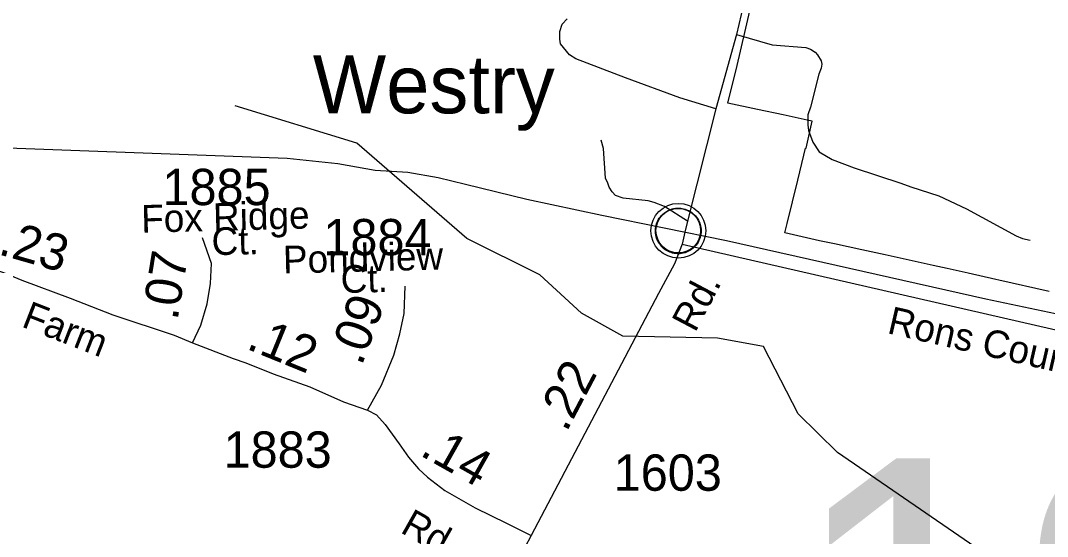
# Model space of a CAD drawing. Extents: x 2220236 to 2384410, y 720751 to 894131.
# Drawn here: x 2323811 to 2327342, y 806242 to 808018 of the extents above; entities that cross this region are included whole.
import ezdxf

# ---------------------------------------------------------------- set-up
doc = ezdxf.new("R2010")
doc.units = 0
doc.layers.add('Default', color=7, linetype='Continuous')

msp = doc.modelspace()

# ---------------------------------------------------------------- linework, layer by layer
at = {"layer": 'Default'}
for points in [[(2326568.2, 810272.9), (2326569.8, 810183), (2326568.1, 810143.3), (2326561.5, 810070.5), (2326543.3, 809895.2), (2326531.8, 809757.9), (2326513.6, 809552.8), (2326498.7, 809339.5), (2326493.8, 809233.6), (2326479.7, 809112.1), (2326464.8, 808978.1), (2326446.7, 808814.4), (2326408.6, 808584.5), (2326390.5, 808490.2), (2326369, 808399.3), (2326345.6, 808281.4), (2326273, 807970.7), (2326201.9, 807714.1), (2326104, 807327.2), (2326095.2, 807289.9)], [(2327347.8, 807086.1), (2327175, 807124.6), (2327164.2, 807127), (2327069.8, 807148.3), (2326997.2, 807164.6), (2326948.8, 807175.4), (2326804.8, 807207.2), (2326784.5, 807211.6), (2326703.5, 807229.1), (2326609.8, 807249.3), (2326558.5, 807260.3), (2326439.2, 807287), (2326447.2, 807319.7), (2326483.5, 807468.9), (2326504.2, 807554.4), (2326510.2, 807579.1), (2326512.8, 807579.1), (2326533.2, 807671.8), (2326516, 807675.5), (2326433.2, 807693.2), (2326345, 807712), (2326243.2, 807733.7), (2326274.8, 807863), (2326301.2, 807976.9), (2326331.5, 808107.6)], [(2327347.8, 807086.1), (2327175, 807124.6), (2327164.2, 807127), (2327069.8, 807148.3), (2326997.2, 807164.6), (2326948.8, 807175.4), (2326804.8, 807207.2), (2326784.5, 807211.6), (2326703.5, 807229.1), (2326609.8, 807249.3), (2326558.5, 807260.3), (2326439.2, 807287), (2326447.2, 807319.7), (2326483.5, 807468.9), (2326504.2, 807554.4), (2326510.2, 807579.1), (2326512.8, 807579.1), (2326533.2, 807671.8), (2326516, 807675.5), (2326433.2, 807693.2), (2326345, 807712), (2326243.2, 807733.7), (2326274.8, 807863), (2326301.2, 807976.9), (2326331.5, 808107.6)], [(2326201.9, 807714.1), (2326077.5, 807752.6), (2325890.8, 807820.6), (2325720.3, 807886.9), (2325698.1, 807900.6), (2325667.6, 807938.2), (2325665.5, 807954.3), (2325665.3, 807980.3), (2325673, 808006.2), (2325690.6, 808024.5)], [(2326273, 807970.7), (2326395.4, 807934.1), (2326511.4, 807925.4), (2326527.4, 807919.5), (2326543.6, 807909.7), (2326551.6, 807899.8), (2326563.8, 807879.9), (2326565.9, 807868), (2326564.1, 807853.9), (2326556.3, 807833.8), (2326527.6, 807719.6), (2326517.8, 807693.4), (2326518.2, 807659.6), (2326520.4, 807639.5), (2326534.9, 807599.7), (2326557.2, 807566), (2326601.5, 807540.4), (2326677.7, 807511.3), (2326838.3, 807459), (2326872.5, 807445.4), (2326968.8, 807414.5), (2327063.2, 807369.6), (2327234, 807277.3), (2327256.2, 807267.6), (2327282.3, 807261.9)], [(2318345.2, 807751.5), (2319665, 807707.7), (2320578.7, 807687.5), (2321488.8, 807653.4), (2322722.5, 807614.6), (2323518.4, 807589.3), (2324728.3, 807544.3), (2324902.4, 807526.2), (2325030.8, 807503.6), (2325142.6, 807496.8), (2325246.8, 807477.8), (2325341, 807454.9), (2325551.4, 807403.2), (2325809.9, 807348), (2326238.6, 807260.7), (2327130.5, 807060.4), (2328066, 806862.6), (2329318.5, 806586.2), (2329681.9, 806506.8), (2329765.5, 806488.4), (2329846, 806471)], [(2327373.9, 806063.9), (2327132, 806178.7), (2326619.9, 806532), (2326485, 806664.3), (2326365.9, 806895.8), (2326207, 806925.3), (2325881.9, 806931.8), (2325739.8, 807011.3), (2325596.9, 807143.3), (2325345.9, 807267.6), (2324967, 807596.7), (2324548.9, 807724.1)], [(2326104, 807327.2), (2326025.5, 807378.4), (2325989.4, 807391.9), (2325969.3, 807397.7), (2325883.3, 807406.8), (2325857.1, 807416.5), (2325845, 807428.4), (2325835, 807444.2), (2325830.8, 807458.3), (2325822.5, 807476.1), (2325815.5, 807578.1), (2325807.2, 807605.9)], [(2326095.2, 807289.9), (2326085.5, 807249), (2326059.1, 807181.2), (2326004.5, 807078.6), (2325566.3, 806246.1)], [(2324402.7, 806908.8), (2324431.3, 806970), (2324452.4, 807042.6), (2324463.8, 807113.4), (2324467.7, 807182.2), (2324437.1, 807270.2)], [(2326085.5, 807249), (2327880.4, 806836.6), (2328201.1, 806770), (2328830.1, 806646.9), (2328928.4, 806619.9), (2328946.3, 806612.2), (2328974.8, 806582.4), (2328987, 806562.7), (2328999.1, 806550.8), (2329023.4, 806518.9), (2329076, 806469.7), (2329104, 806459.8), (2329260.3, 806413.6), (2329290.6, 806402)], [(2323230.7, 807245.2), (2323276.2, 807219.9), (2323331.6, 807189.3), (2323369.8, 807181.7), (2323440.6, 807183.6), (2323515.1, 807191.2), (2323574.3, 807197), (2323608.7, 807195.1), (2323662.3, 807179.8), (2323752.1, 807151.1), (2323815.2, 807124.3), (2323981.4, 807063.1), (2324128.6, 807005.8), (2324338.8, 806935), (2324402.7, 806908.8)], [(2325004.3, 806677.7), (2325052, 806763.7), (2325094.1, 806867), (2325115.1, 806939.7), (2325130.3, 807009.9), (2325134.1, 807103.6)], [(2324402.7, 806908.8), (2324541.8, 806855.5), (2324585.7, 806840.2), (2324679.4, 806802), (2324805.5, 806758), (2324922.1, 806706.4), (2325004.3, 806677.7)], [(2325004.3, 806677.7), (2325034.5, 806660.7), (2325065.1, 806628.2), (2325112.9, 806561.3), (2325145.3, 806515.4), (2325179.7, 806475.3), (2325210.3, 806446.6), (2325269.6, 806400.7), (2325374.7, 806341.4), (2325481.7, 806287.9), (2325566.3, 806246.1)], [(2325566.3, 806246.1), (2325392.1, 805915.1), (2325262.5, 805626.4), (2324528.6, 804173.5), (2324435.7, 804015.1), (2324349.2, 803896.6), (2324302.1, 803839.5), (2324247.6, 803770), (2324118.9, 803647.6), (2324000.7, 803529.4), (2323914.1, 803455.5)]]:
    msp.add_lwpolyline(points, dxfattribs=at)
msp.add_lwpolyline([(2325995.2, 807307.1), (2325996.2, 807312.7), (2325998, 807319.3), (2326000.9, 807326.5), (2326003.9, 807332.2), (2326007.2, 807337.9), (2326011, 807343.1), (2326014.9, 807347.4), (2326019.5, 807352), (2326025, 807356.6), (2326030.5, 807360.3), (2326035.3, 807363.1), (2326040.4, 807365.6), (2326045.9, 807367.9), (2326051.5, 807369.7), (2326055.8, 807370.9), (2326060.7, 807371.6), (2326064.8, 807372.3), (2326071.2, 807372.6), (2326075.6, 807372.5), (2326081.3, 807372.2), (2326086.2, 807371.5), (2326091.1, 807370.5), (2326096.1, 807369.1), (2326101.2, 807367.2), (2326107.9, 807364.2), (2326114.2, 807360.7), (2326119.2, 807357.2), (2326124.4, 807353.2), (2326127.7, 807350), (2326131.8, 807345.7), (2326135.7, 807341), (2326138.8, 807336.4), (2326141.9, 807331.4), (2326144.3, 807326.2), (2326146.4, 807321.2), (2326147.9, 807316.2), (2326149.2, 807311.6), (2326150.3, 807305.5), (2326150.9, 807300.8), (2326151.2, 807294.8), (2326151, 807289.1), (2326150.5, 807283.4), (2326149.5, 807277.9), (2326147.9, 807271.7), (2326146, 807265.9), (2326143.7, 807260.8), (2326140.5, 807254.8), (2326137.2, 807249.5), (2326133.8, 807244.8), (2326129.6, 807240.1), (2326124.3, 807235.1), (2326119.3, 807231), (2326114.3, 807227.5), (2326109.9, 807225), (2326103.1, 807221.8), (2326096, 807219.1), (2326090, 807217.6), (2326083.4, 807216.3), (2326079, 807215.8), (2326074.5, 807215.6), (2326068.9, 807215.6), (2326064.6, 807216), (2326059, 807216.7), (2326053.1, 807218), (2326048.5, 807219.3), (2326043.3, 807221.2), (2326038.7, 807223.2), (2326034.8, 807225.4), (2326028, 807229.5), (2326022.4, 807233.8), (2326017.5, 807238.3), (2326013.1, 807243.1), (2326009.9, 807247.1), (2326006.9, 807251.3), (2326002.8, 807258.4), (2326001.1, 807261.9), (2325999.4, 807265.9), (2325996.8, 807274.1), (2325995.2, 807281.2), (2325994.6, 807286.3), (2325994.2, 807292.7), (2325994.2, 807297.3), (2325994.7, 807303.8)], close=True, dxfattribs=at)
for centre, radius in [((2326072.9, 807294.7), 94.3), ((2326072.6, 807295), 76.7)]:
    msp.add_circle(centre, radius, dxfattribs=at)

# ---------------------------------------------------------------- texts
for s, height, p in [('Westry', 200, (2324815.9, 807698.9)), ('1885', 125, (2324299.1, 807382.8)), ('1884', 125, (2324852.3, 807210.2)), ('1883', 125, (2324509.2, 806479)), ('1603', 125, (2325850.6, 806399.7)), ('192', 1066.27, (2326453.9, 805445.6))]:
    msp.add_text(s, height=height, dxfattribs=at).set_placement(p)
for s, height, rotation, p in [('Fox Ridge', 95, 1.4273, (2324227, 807288)), ('.23', 125, 344.0482, (2323730.8, 807214.7)), ('Ct.', 95, 1.4273, (2324469.1, 807210.4)), ('Pondview', 95, 1.4273, (2324714.4, 807147.5)), ('.07', 125, 80.7929, (2324350.7, 806983.5)), ('Ct.', 95, 1.4273, (2324912.8, 807080.1)), ('Rd.', 95, 62.1596, (2326130.6, 806941.6)), ('Farm', 95, 338.7051, (2323810.9, 806965.8)), ('.09', 125, 69.4732, (2324983.8, 806826.9)), ('Rons Country Ln', 95, 347.0617, (2326787.8, 806942.7)), ('.12', 125, 337.7879, (2324583.7, 806889.8)), ('.22', 125, 62.2414, (2325687.8, 806598.5)), ('.14', 125, 330.5821, (2325180.3, 806523.8)), ('Rd.', 95, 330.5821, (2325113.5, 806258))]:
    msp.add_text(s, height=height, rotation=rotation, dxfattribs=at).set_placement(p)

doc.saveas('drawing.dxf')
